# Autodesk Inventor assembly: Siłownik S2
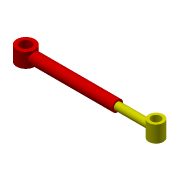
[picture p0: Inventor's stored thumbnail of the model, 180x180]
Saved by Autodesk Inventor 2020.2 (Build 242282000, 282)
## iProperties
Manager: www.cadconsulting.pl
Company: Fabian Stasiak CAD Consulting
Created: 2006-08
Part Number: Siłownik S2
Document SubType Name: Assembly
Designer: F.Stasiak
Author: F.Stasiak
Subject: Zbiór ćwiczeń. Autodesk Inventor 2020. Kurs podstawowy
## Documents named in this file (3)
- C:\2020_Kurs_podstawowy\R6 Zespoły\Lustro\Siłownik S2.iam
- C:\2020_Kurs_podstawowy\R6 Zespoły\Lustro\Cyl2.ipt
- C:\2020_Kurs_podstawowy\R6 Zespoły\Lustro\T2.ipt
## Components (2 placed, 2 different names)
1. Cyl2:1 — Zestawiający:1
2. T2:1 — Zestawiający:1
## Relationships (1: Mate 1)
- Zestawiający:1 [Mate]: Cyl2:1 ↔ T2:1
